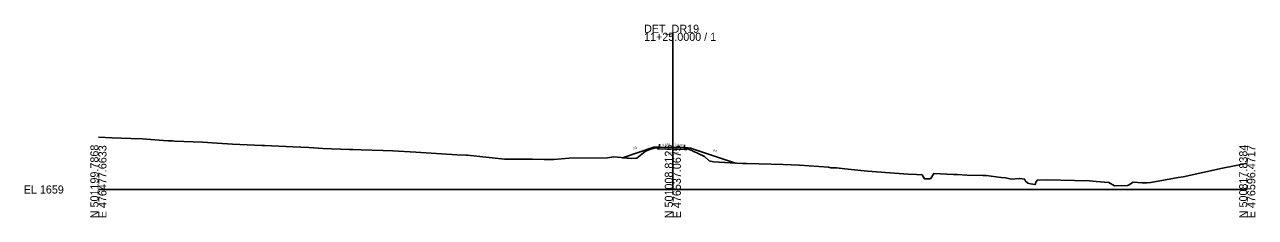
# Model space of a CAD drawing. Extents: x -26 to 403, y -10 to 3059.
# Drawn here: x -25.7 to 402.8, y 1990.3 to 2057.4 of the extents above; entities that cross this region are included whole.
import ezdxf

# ---------------------------------------------------------------- set-up
doc = ezdxf.new("R2010")
doc.units = 0
for name, color, linetype in [('Exist Cross Section Cell', 7, 'Continuous'), ('Exist XS Center Line Elevation Label', 7, 'Continuous'), ('Exist XS Ground Line', 7, 'Continuous'), ('Prop XS Dump Level', 7, 'Continuous'), ('Prop XS Earthwork Shape', 7, 'Continuous'), ('Prop XS EOT Tick Mark', 7, 'Continuous'), ('Prop XS Finish Grade', 7, 'Continuous'), ('Prop XS Finish Grade Earthwork', 7, 'Continuous'), ('Prop XS Finish Grade Pavement', 7, 'Continuous'), ('Prop XS Hydro Fill Slope Data', 7, 'Continuous'), ('Prop XS Pvmt Edge Slope', 7, 'Continuous'), ('Prop XS SE Text', 7, 'Continuous'), ('Prop XS Shoulder Borrow Shape', 7, 'Continuous'), ('Prop XS Side Slope Text', 7, 'Continuous'), ('Prop XS Subgrade Earthwork', 7, 'Continuous')]:
    doc.layers.add(name, color=color, linetype=linetype)

msp = doc.modelspace()

# ---------------------------------------------------------------- linework, layer by layer
at = {"layer": 'Exist Cross Section Cell'}
for p, q in [((200, 2000), (200, 2054.54)), ((0, 2000), (200, 2000)), ((200, 2000), (400, 2000))]:
    msp.add_line(p, q, dxfattribs=at)
at = {"layer": 'Exist XS Ground Line'}
msp.add_lwpolyline([(0, 2018.18), (4.8, 2018.03), (11.26, 2017.81), (15.27, 2017.63), (24.16, 2017), (25.75, 2016.89), (26.46, 2016.84), (36.22, 2016.44), (41.35, 2016.17), (46.7, 2015.81), (56.87, 2015.37), (57.17, 2015.36), (57.84, 2015.32), (67.65, 2014.82), (73.31, 2014.62), (78.12, 2014.3), (87.28, 2013.92), (88.59, 2013.88), (91.51, 2013.8), (99.07, 2013.6), (102.48, 2013.46), (110.5, 2012.97), (124.84, 2012.12), (128.05, 2011.95), (128.49, 2011.9), (141.45, 2010.53), (143.46, 2010.58), (151.09, 2010.54), (155.24, 2010.43), (158.6, 2010.5), (163.88, 2010.92), (177.27, 2011.08), (179.45, 2011.32), (185.75, 2010.82), (187.45, 2010.91), (190.38, 2013.25), (191.93, 2013.93), (193.95, 2014.5), (194.82, 2014.77), (195.52, 2014.75), (200, 2014.66), (203.56, 2014.58), (205.67, 2013.91), (206.88, 2013.52), (211.04, 2011.48), (212.65, 2009.99), (214.11, 2009.64), (224.21, 2009.05), (225.32, 2009.02), (225.73, 2009.05), (238.38, 2008.7), (244.08, 2008.46), (254.17, 2007.73), (255.03, 2007.56), (257, 2007.54), (259.88, 2007.24), (266.66, 2006.45), (267.8, 2006.37), (281.91, 2005.38), (284.9, 2005.24), (286.78, 2005.11), (287.27, 2004.33), (287.61, 2003.73), (288.82, 2003.75), (289.72, 2003.76), (290.16, 2004.47), (290.85, 2005.52), (297.68, 2005.18), (299.01, 2005.18), (302.33, 2005.04), (307.95, 2004.92), (308.32, 2004.93), (309.13, 2004.88), (314.35, 2004.18), (315.8, 2004.02), (317.77, 2003.65), (320.76, 2003.89), (322.52, 2003.57), (322.65, 2003.06), (323.58, 2002.26), (324.58, 2002), (326.15, 2001.71), (326.45, 2002.54), (326.96, 2003.26), (330.25, 2003.42), (339.84, 2003.12), (343.03, 2003.07), (343.87, 2003.09), (347.37, 2002.75), (351.83, 2002.45), (353.75, 2001.3), (358.33, 2001.39), (358.69, 2001.55), (360.32, 2002.51), (363.47, 2002.33), (365.19, 2002.31), (366.4, 2002.49), (375.99, 2004.18), (377.75, 2004.42), (391.39, 2007.4), (395.52, 2008.25), (400, 2009.18)], dxfattribs=at)
at = {"layer": 'Prop XS Dump Level'}
for p, q in [((195.38, 2014.77), (200, 2014.68)), ((200, 2014.68), (204.1, 2014.6))]:
    msp.add_line(p, q, dxfattribs=at)
at = {"layer": 'Prop XS Earthwork Shape'}
for points in [[(193.38, 2014.69), (182.52, 2011.07), (185.75, 2010.82), (187.45, 2010.91), (190.38, 2013.25), (191.93, 2013.93), (193.95, 2014.5), (194.25, 2014.59), (194.12, 2014.72)], [(204.1, 2013.93), (204.78, 2013.92), (204.99, 2014.13), (203.56, 2014.58), (200, 2014.66), (195.52, 2014.75), (194.82, 2014.77), (194.25, 2014.59), (194.72, 2014.12), (195.38, 2014.11), (200, 2014.01)], [(206.88, 2013.52), (211.04, 2011.48), (212.65, 2009.99), (214.11, 2009.64), (221.85, 2009.19), (206.1, 2014.44), (205.36, 2014.5), (204.99, 2014.13), (205.67, 2013.91)]]:
    msp.add_lwpolyline(points, close=True, dxfattribs=at)
at = {"layer": 'Prop XS EOT Tick Mark'}
for p, q in [((195.38, 2014.77), (195.38, 2015.77)), ((204.1, 2014.6), (204.1, 2015.6))]:
    msp.add_line(p, q, dxfattribs=at)
at = {"layer": 'Prop XS Finish Grade'}
for p, q in [((195.38, 2014.77), (194.12, 2014.72)), ((204.1, 2014.6), (205.36, 2014.5))]:
    msp.add_line(p, q, dxfattribs=at)
at = {"layer": 'Prop XS Finish Grade Earthwork'}
for p, q in [((193.38, 2014.69), (182.52, 2011.07)), ((194.12, 2014.72), (193.38, 2014.69)), ((205.36, 2014.5), (206.1, 2014.44)), ((206.1, 2014.44), (221.85, 2009.19))]:
    msp.add_line(p, q, dxfattribs=at)
at = {"layer": 'Prop XS Finish Grade Pavement'}
for p, q in [((195.38, 2014.77), (200, 2014.68)), ((200, 2014.68), (204.1, 2014.6))]:
    msp.add_line(p, q, dxfattribs=at)
at = {"layer": 'Prop XS Hydro Fill Slope Data'}
msp.add_line((206.1, 2014.44), (221.85, 2009.19), dxfattribs=at)
at = {"layer": 'Prop XS Pvmt Edge Slope'}
for p, q in [((195.38, 2014.77), (194.72, 2014.12)), ((204.1, 2014.6), (204.78, 2013.92))]:
    msp.add_line(p, q, dxfattribs=at)
at = {"layer": 'Prop XS Shoulder Borrow Shape'}
for points in [[(195.38, 2014.77), (194.72, 2014.12), (194.12, 2014.72)], [(204.78, 2013.92), (205.36, 2014.5), (204.1, 2014.6)]]:
    msp.add_lwpolyline(points, close=True, dxfattribs=at)
at = {"layer": 'Prop XS Subgrade Earthwork'}
for p, q in [((194.72, 2014.12), (194.12, 2014.72)), ((195.38, 2014.11), (194.72, 2014.12)), ((200, 2014.01), (195.38, 2014.11)), ((204.78, 2013.92), (205.36, 2014.5)), ((204.1, 2013.93), (200, 2014.01)), ((204.1, 2013.93), (204.78, 2013.92))]:
    msp.add_line(p, q, dxfattribs=at)

# ---------------------------------------------------------------- texts
at = {"layer": 'Exist Cross Section Cell'}
for s, p in [('DET_DR19', (190, 2054.54)), ('11+25.0000 / 1', (190, 2051.74)), ('EL 1659', (-26, 1998.6))]:
    msp.add_text(s, height=2.8, dxfattribs=at).set_placement(p)
for s, p in [('N 501199.7868', (0, 1990)), ('E 476477.6633', (2.8, 1990)), ('N 501008.8126', (200, 1990)), ('E 476537.0675', (202.8, 1990)), ('N 500817.8384', (400, 1990)), ('E 476596.4717', (402.8, 1990))]:
    msp.add_text(s, height=2.8, rotation=90, dxfattribs=at).set_placement(p)
at = {"layer": 'Exist XS Center Line Elevation Label'}
msp.add_text('1673.66', height=0.75, dxfattribs=at).set_placement((198.27, 2012.28))
at = {"layer": 'Prop XS Dump Level'}
for p in [(193.38, 2014.65), (206.1, 2014.4)]:
    msp.add_text('Case1', height=0.04, dxfattribs=at).set_placement(p)
at = {"layer": 'Prop XS SE Text'}
for p in [(196.38, 2015.25), (200.74, 2015.17)]:
    msp.add_text('0.020', height=0.75, rotation=358.8542, dxfattribs=at).set_placement(p)
at = {"layer": 'Prop XS Side Slope Text'}
for rotation, p in [(18.4349, (186.25, 2013.9)), (341.5798, (213.89, 2013.43))]:
    msp.add_text('3:1', height=0.75, rotation=rotation, dxfattribs=at).set_placement(p)

doc.saveas('drawing.dxf')
